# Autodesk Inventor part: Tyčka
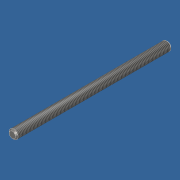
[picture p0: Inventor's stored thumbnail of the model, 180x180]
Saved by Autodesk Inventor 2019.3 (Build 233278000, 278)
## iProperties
Created: 2019-02
Part Number: Tyčka
Material: Ocel, litá
Document SubType Name: Modeling
Designer: B-hon
Density: 7.85 g/cm^3
Appearance: Pololeštěná
Author: B-hon
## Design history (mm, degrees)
sketch "Náčrt1"
  geometry: C1 r 5 at (0, 0); 1 further point
  constraints: 1 centre point, 1 coincident
  dimensions: "d0" = 10 diameter of C1
extrude "Vysunutí1" new body sketch "Náčrt1" distance "d1" = 172; taper "d2" = 0 deg
feature "Závit1" dims "d3" = 10, "d4" = 0
chamfer "Zkosení1" distance "d5" = 1.5; stored, may be unused: second distance "d6" = 2, angle "d7" = 45 deg
node "Těleso1"
